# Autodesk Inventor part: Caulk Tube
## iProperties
Created: 2009-03
Part Number: Caulk Tube
Document SubType Name: Modeling
Designer: tangg
Density: 3.18 g/cm^3
Material: Silicon Nitride
Mass: 657.694 g
Surface Area: 779.569 cm^2
Volume: 206.822 cm^3
Author: tangg
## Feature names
1. Revolution1
2. Extrusion1
3. Revolution2
4. Revolution3
